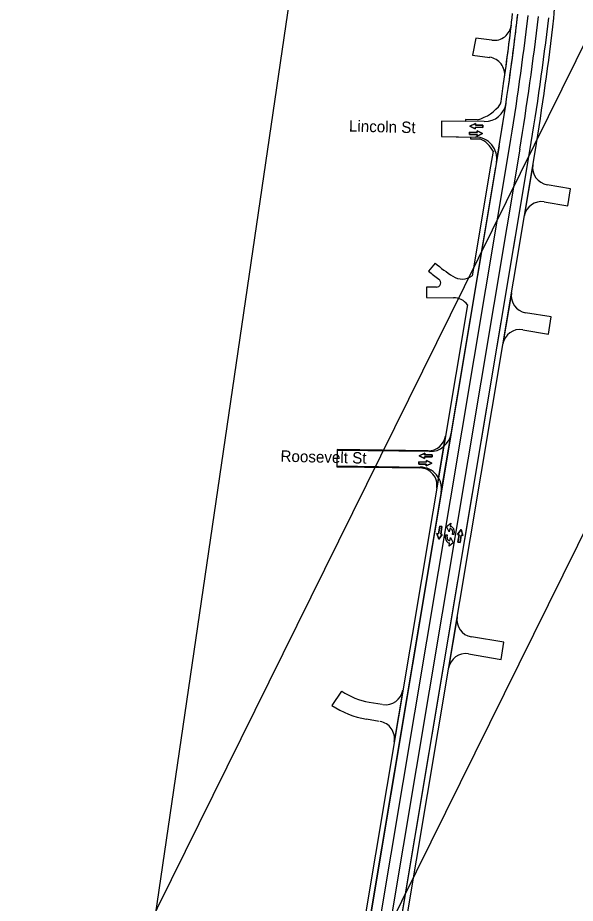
# Model space of a CAD drawing. Extents: x 14104283 to 14129344, y 8637090 to 8673339.
# Drawn here: x 14118632 to 14119277, y 8669277 to 8670301 of the extents above; entities that cross this region are included whole.
import ezdxf

# ---------------------------------------------------------------- set-up
doc = ezdxf.new("R2010")
doc.units = 0
for name, color, linetype in [('Cell', 7, 'Continuous'), ('dsnNonPlotable', 7, 'Continuous'), ('dsnPaintExistingEdgeLineRightWhite', 7, 'Continuous'), ('dsnPaintExistingNoPassingYellow', 7, 'Continuous'), ('dsnShadingPaved', 7, 'Continuous'), ('dsnStgShadingPrevPav', 7, 'Continuous'), ('dsnTextFinalPlan', 7, 'Continuous'), ('Level 2', 7, 'Continuous'), ('Level 5', 7, 'Continuous')]:
    doc.layers.add(name, color=color, linetype=linetype)

msp = doc.modelspace()

# ---------------------------------------------------------------- linework, layer by layer
at = {"layer": 'Cell'}
for p, q in [((14119131.8, 8669710.3), (14119131.5, 8669710.3)), ((14119131.9, 8669712.9), (14119132.1, 8669712.9)), ((14119131.2, 8669693.7), (14119131, 8669693.7)), ((14119131.3, 8669696.4), (14119131.6, 8669696.3))]:
    msp.add_line(p, q, dxfattribs=at)
for points in [[(14119127.6, 8669712.8), (14119132.5, 8669716.5), (14119131.9, 8669712.9)], [(14119127.6, 8669712.8), (14119132.5, 8669716.5), (14119131.9, 8669712.9)], [(14119131.5, 8669710.3), (14119130.9, 8669706.7), (14119127.6, 8669712.8)], [(14119131.5, 8669710.3), (14119130.9, 8669706.7), (14119127.6, 8669712.8)], [(14119131.8, 8669710.3), (14119131.5, 8669710.3)], [(14119131.9, 8669712.9), (14119132.1, 8669712.9)], [(14119136.5, 8669707.1), (14119136.1, 8669703.4), (14119134.6, 8669703.6), (14119134.9, 8669706.2)], [(14119136.5, 8669707.1), (14119136.1, 8669703.4), (14119134.6, 8669703.6), (14119134.9, 8669706.2)], [(14119126.6, 8669699.5), (14119127, 8669703.2), (14119128.5, 8669703), (14119128.2, 8669700.4)], [(14119126.6, 8669699.5), (14119127, 8669703.2), (14119128.5, 8669703), (14119128.2, 8669700.4)], [(14119131.6, 8669696.3), (14119132.2, 8669700), (14119135.5, 8669693.8)], [(14119131.6, 8669696.3), (14119132.2, 8669700), (14119135.5, 8669693.8)], [(14119135.5, 8669693.8), (14119130.6, 8669690.1), (14119131.2, 8669693.7)], [(14119135.5, 8669693.8), (14119130.6, 8669690.1), (14119131.2, 8669693.7)], [(14119131.2, 8669693.7), (14119131, 8669693.7)], [(14119131.3, 8669696.4), (14119131.6, 8669696.3)]]:
    msp.add_lwpolyline(points, dxfattribs=at)
for centre, major_axis in [((14119131.4, 8669706.6), (-0.4, -3.66)), ((14119131.4, 8669706.6), (-0.4, -3.66)), ((14119131.5, 8669707.6), (-0.58, -5.22)), ((14119131.5, 8669707.6), (-0.58, -5.22)), ((14119131.6, 8669699), (0.58, 5.22)), ((14119131.6, 8669699), (0.58, 5.22)), ((14119131.7, 8669700), (0.4, 3.66)), ((14119131.7, 8669700), (0.4, 3.66))]:
    msp.add_ellipse(centre, major_axis=major_axis, ratio=0.9474, start_param=1.570796, end_param=3.141593, dxfattribs=at)
at = {"layer": 'dsnNonPlotable'}
for points in [[(14118774.2, 8669147.8), (14119001.7, 8670698.7), (14119501.3, 8670625.4), (14119273.8, 8669074.5)], [(14118631.6, 8668945.1), (14119326.4, 8670350.2), (14120231.7, 8669902.6), (14119537, 8668497.5)], [(14118855.7, 8668834.3), (14119550.5, 8670239.4), (14120003.2, 8670015.6), (14119308.4, 8668610.5)]]:
    msp.add_lwpolyline(points, close=True, dxfattribs=at)
at = {"layer": 'dsnPaintExistingEdgeLineRightWhite'}
msp.add_line((14119184.5, 8670128.2), (14119019.2, 8669141.3), dxfattribs=at)
msp.add_line((14119184.5, 8670128.2), (14119019.2, 8669141.3), dxfattribs=at)
msp.add_lwpolyline([(14119029.9, 8669002.7), (14119054.7, 8669135.4), (14119224.2, 8670147)], dxfattribs=at)
msp.add_lwpolyline([(14119029.9, 8669002.7), (14119054.7, 8669135.4), (14119224.2, 8670147)], dxfattribs=at)
for radius, start in [(2982, 351.8737), (3018, 350.4915)]:
    msp.add_arc((14116247.6, 8670645.6), radius, start, 353.4443, dxfattribs=at)
at = {"layer": 'dsnPaintExistingNoPassingYellow'}
for p, q in [((14119031.1, 8669139.3), (14119200.5, 8670151)), ((14119212.3, 8670149), (14119042.9, 8669137.4))]:
    msp.add_line(p, q, dxfattribs=at)
for radius in [2994, 3006]:
    msp.add_arc((14116247.6, 8670645.6), radius, 350.4915, 353.4443, dxfattribs=at)
at = {"layer": 'dsnShadingPaved'}
for p, q in [((14119185.5, 8670133.9), (14119196.5, 8670202.2)), ((14119122, 8670181.5), (14119121.8, 8670163.6)), ((14119171.4, 8670180.9), (14119122, 8670181.5)), ((14119121.8, 8670163.6), (14119161.1, 8670163)), ((14119188.7, 8670152.9), (14119019.2, 8669141.2)), ((14119031, 8669139.3), (14119200.5, 8670150.9)), ((14119031.1, 8669139.3), (14119200.5, 8670151)), ((14119212.3, 8670149), (14119042.9, 8669137.4)), ((14119212.3, 8670149), (14119042.9, 8669137.4)), ((14119054.7, 8669135.4), (14119224.2, 8670147)), ((14119121.6, 8669752.3), (14119132.9, 8669820.2)), ((14119001.1, 8669800.8), (14119000.9, 8669782.8)), ((14119107.9, 8669799.3), (14119001.1, 8669800.8)), ((14119000.9, 8669782.8), (14119097.2, 8669781.4))]:
    msp.add_line(p, q, dxfattribs=at)
for centre, radius, start, end in [((14116247.6, 8670645.5), 2982, 350.4915, 353.4443), ((14116247.6, 8670645.6), 2994, 350.4915, 353.4443), ((14116247.6, 8670645.5), 2994, 350.4915, 353.4443), ((14116247.6, 8670645.6), 3006, 350.4915, 353.4443), ((14116247.6, 8670645.6), 3006, 350.4915, 353.4443), ((14116247.6, 8670645.6), 3018, 350.4915, 353.4443), ((14119171.8, 8670205.9), 25, 269.2381, 351.4482), ((14119160.8, 8670138), 25, 350.4915, 89.2381), ((14119108.3, 8669824.3), 25, 269.2165, 350.4915), ((14119096.9, 8669756.4), 25, 350.4915, 89.2165)]:
    msp.add_arc(centre, radius, start, end, dxfattribs=at)
at = {"layer": 'dsnStgShadingPrevPav'}
for p, q in [((14119161.4, 8670277.5), (14119157.8, 8670257.8)), ((14119180.2, 8670275), (14119161.4, 8670277.5)), ((14119157.8, 8670257.8), (14119177.6, 8670255.2)), ((14119122, 8670181.5), (14119121.8, 8670163.6)), ((14119149.5, 8670181.2), (14119122, 8670181.5)), ((14119149.6, 8670183.2), (14119149.5, 8670181.2)), ((14119163.6, 8670183), (14119149.6, 8670183.2)), ((14119121.8, 8670163.6), (14119155.3, 8670163.1)), ((14119155.3, 8670163.1), (14119155.3, 8670161.1)), ((14119155.3, 8670161.1), (14119166.1, 8670161)), ((14119060.6, 8669134.4), (14119230.1, 8670146.1)), ((14119181.6, 8670146.9), (14119178.6, 8670129.2)), ((14119178.6, 8670129.2), (14119157.4, 8670002.4)), ((14119227.6, 8670130.9), (14119217.6, 8670071.7)), ((14119271.2, 8670103.3), (14119244, 8670107.9)), ((14119267.9, 8670083.6), (14119271.2, 8670103.3)), ((14119240.7, 8670088.1), (14119267.9, 8670083.6)), ((14119114.6, 8670017.2), (14119106.8, 8670008.1)), ((14119104.7, 8669989.6), (14119104.6, 8669977.6)), ((14119115.9, 8669989.5), (14119104.7, 8669989.6)), ((14119104.6, 8669977.6), (14119135.8, 8669977.3)), ((14119202.8, 8669982.9), (14119192.9, 8669923.8)), ((14119151.8, 8669969.1), (14119013.3, 8669142.3)), ((14119248.8, 8669955), (14119219.2, 8669959.9)), ((14119245.5, 8669935.2), (14119248.8, 8669955)), ((14119216, 8669940.2), (14119245.5, 8669935.2)), ((14119116.3, 8669757.1), (14119126.3, 8669817)), ((14119001.1, 8669801.8), (14119000.8, 8669781.8)), ((14119106.3, 8669800.3), (14119001.1, 8669801.8)), ((14119000.8, 8669781.8), (14119096.8, 8669780.4)), ((14119140, 8669608.2), (14119130.1, 8669549)), ((14119194, 8669578.8), (14119156.4, 8669585.1)), ((14119190.7, 8669559.1), (14119194, 8669578.8)), ((14119153.1, 8669565.4), (14119190.7, 8669559.1)), ((14119077.1, 8669523.4), (14119067.2, 8669464.2)), ((14118995.2, 8669505.9), (14119006.4, 8669522.4)), ((14119038.3, 8669509.6), (14119053.1, 8669507.1)), ((14119049.8, 8669487.4), (14119035, 8669489.9))]:
    msp.add_line(p, q, dxfattribs=at)
for centre, radius, start, end in [((14116247.6, 8670645.6), 2976, 351.8742, 353.4443), ((14119182.8, 8670294.9), 20, 262.604, 353.1855), ((14116247.6, 8670645.6), 2976, 352.0225, 353.1855), ((14116247.6, 8670645.6), 3024, 350.4915, 353.4443), ((14119175, 8670235.4), 20, 352.0225, 82.604), ((14116247.6, 8670645.6), 2976, 351.4136, 351.8742), ((14119150.2, 8670231.2), 50, 285.4983, 323.2854), ((14119154.9, 8670133.1), 30, 27.3614, 68.1986), ((14119247.3, 8670127.6), 20, 170.4915, 260.4915), ((14119237.4, 8670068.4), 20, 80.4915, 170.4915), ((14119240.4, 8670164.9), 194, 229.5568, 237.1074), ((14119240.4, 8670164.9), 206, 229.5568, 233.8406), ((14119115.9, 8669994.5), 5, 269.4915, 53.8406), ((14119145.9, 8670018.8), 20, 237.1074, 304.9185), ((14119135.6, 8669957.3), 20, 36.0645, 89.4915), ((14119222.5, 8669979.6), 20, 170.4915, 260.4915), ((14119212.6, 8669920.5), 20, 80.4915, 170.4915), ((14119106.6, 8669820.3), 20, 269.2165, 350.4915), ((14119096.6, 8669760.4), 20, 350.4915, 89.2165), ((14119159.7, 8669604.9), 20, 170.4915, 260.4915), ((14119149.8, 8669545.7), 20, 80.4915, 170.4915), ((14119057.4, 8669526.7), 20, 260.4915, 350.4915), ((14119051.5, 8669588.5), 80, 235.6951, 260.4915), ((14119051.5, 8669588.5), 100, 235.6951, 260.4915), ((14119047.5, 8669467.5), 20, 350.4915, 80.4915)]:
    msp.add_arc(centre, radius, start, end, dxfattribs=at)
msp.add_open_spline([(14119251.9, 8670300.4), (14119252, 8670302.9), (14119252.4, 8670307.9), (14119252.8, 8670315.5), (14119253.3, 8670323), (14119253.7, 8670330.6), (14119254.1, 8670338.1), (14119254.5, 8670345.7), (14119254.8, 8670353.2), (14119255.2, 8670360.8), (14119255.5, 8670368.3), (14119255.8, 8670375.9), (14119256.1, 8670383.5), (14119256.4, 8670391), (14119256.6, 8670398.6), (14119256.9, 8670406.1), (14119257.1, 8670413.7), (14119257.3, 8670421.2), (14119257.5, 8670428.8), (14119257.6, 8670436.3), (14119257.8, 8670443.9), (14119257.8, 8670448.9), (14119257.9, 8670451.4)], degree=3, dxfattribs=at)
at = {"layer": 'Level 2'}
for points in [[(14119169.7, 8670174.2), (14119169.7, 8670176.7), (14119161, 8670176.8), (14119161, 8670178.7), (14119154.7, 8670175.7), (14119160.9, 8670172.5), (14119161, 8670174.3)], [(14119154.3, 8670168.6), (14119154.2, 8670166.1), (14119163, 8670166), (14119163, 8670164.1), (14119169.2, 8670167.2), (14119163, 8670170.4), (14119163, 8670168.5)], [(14119095.6, 8669787.4), (14119095.6, 8669784.9), (14119104.3, 8669784.8), (14119104.3, 8669783), (14119110.6, 8669786), (14119104.4, 8669789.2), (14119104.3, 8669787.3)], [(14119111.1, 8669793.1), (14119111.1, 8669795.6), (14119102.3, 8669795.7), (14119102.4, 8669797.6), (14119096.1, 8669794.5), (14119102.3, 8669791.3), (14119102.3, 8669793.2)], [(14119122.3, 8669712.6), (14119119.8, 8669713), (14119118.5, 8669704.3), (14119116.6, 8669704.6), (14119118.7, 8669697.9), (14119122.8, 8669703.6), (14119120.9, 8669703.9)], [(14119140.9, 8669694.5), (14119143.4, 8669694.1), (14119144.7, 8669702.7), (14119146.6, 8669702.4), (14119144.5, 8669709.1), (14119140.4, 8669703.4), (14119142.2, 8669703.1)]]:
    msp.add_lwpolyline(points, close=True, dxfattribs=at)
at = {"layer": 'Level 5'}
for points in [[(14119161, 8670174.3), (14119160.9, 8670172.5), (14119154.7, 8670175.7), (14119161, 8670178.7), (14119161, 8670176.8), (14119169.7, 8670176.7), (14119169.7, 8670174.2), (14119161, 8670174.3)], [(14119163, 8670168.5), (14119163, 8670170.4), (14119169.2, 8670167.2), (14119163, 8670164.1), (14119163, 8670166), (14119154.2, 8670166.1), (14119154.3, 8670168.6), (14119163, 8670168.5)], [(14119104.3, 8669787.3), (14119104.4, 8669789.2), (14119110.6, 8669786), (14119104.3, 8669783), (14119104.3, 8669784.8), (14119095.6, 8669784.9), (14119095.6, 8669787.4), (14119104.3, 8669787.3)], [(14119102.3, 8669793.2), (14119102.3, 8669791.3), (14119096.1, 8669794.5), (14119102.4, 8669797.6), (14119102.3, 8669795.7), (14119111.1, 8669795.6), (14119111.1, 8669793.1), (14119102.3, 8669793.2)], [(14119120.9, 8669703.9), (14119122.8, 8669703.6), (14119118.7, 8669697.9), (14119116.6, 8669704.6), (14119118.5, 8669704.3), (14119119.8, 8669713), (14119122.3, 8669712.6), (14119120.9, 8669703.9)], [(14119142.2, 8669703.1), (14119140.4, 8669703.4), (14119144.5, 8669709.1), (14119146.6, 8669702.4), (14119144.7, 8669702.7), (14119143.4, 8669694.1), (14119140.9, 8669694.5), (14119142.2, 8669703.1)]]:
    msp.add_lwpolyline(points, dxfattribs=at)

# ---------------------------------------------------------------- texts
at = {"layer": 'dsnTextFinalPlan'}
for s, height, p in [('Lincoln St', 13.12, (14119014.7, 8670169.4)), ('Roosevelt St', 13.125, (14118935.5, 8669787.7))]:
    msp.add_text(s, height=height, rotation=358.6374, dxfattribs=at).set_placement(p)

doc.saveas('drawing.dxf')
